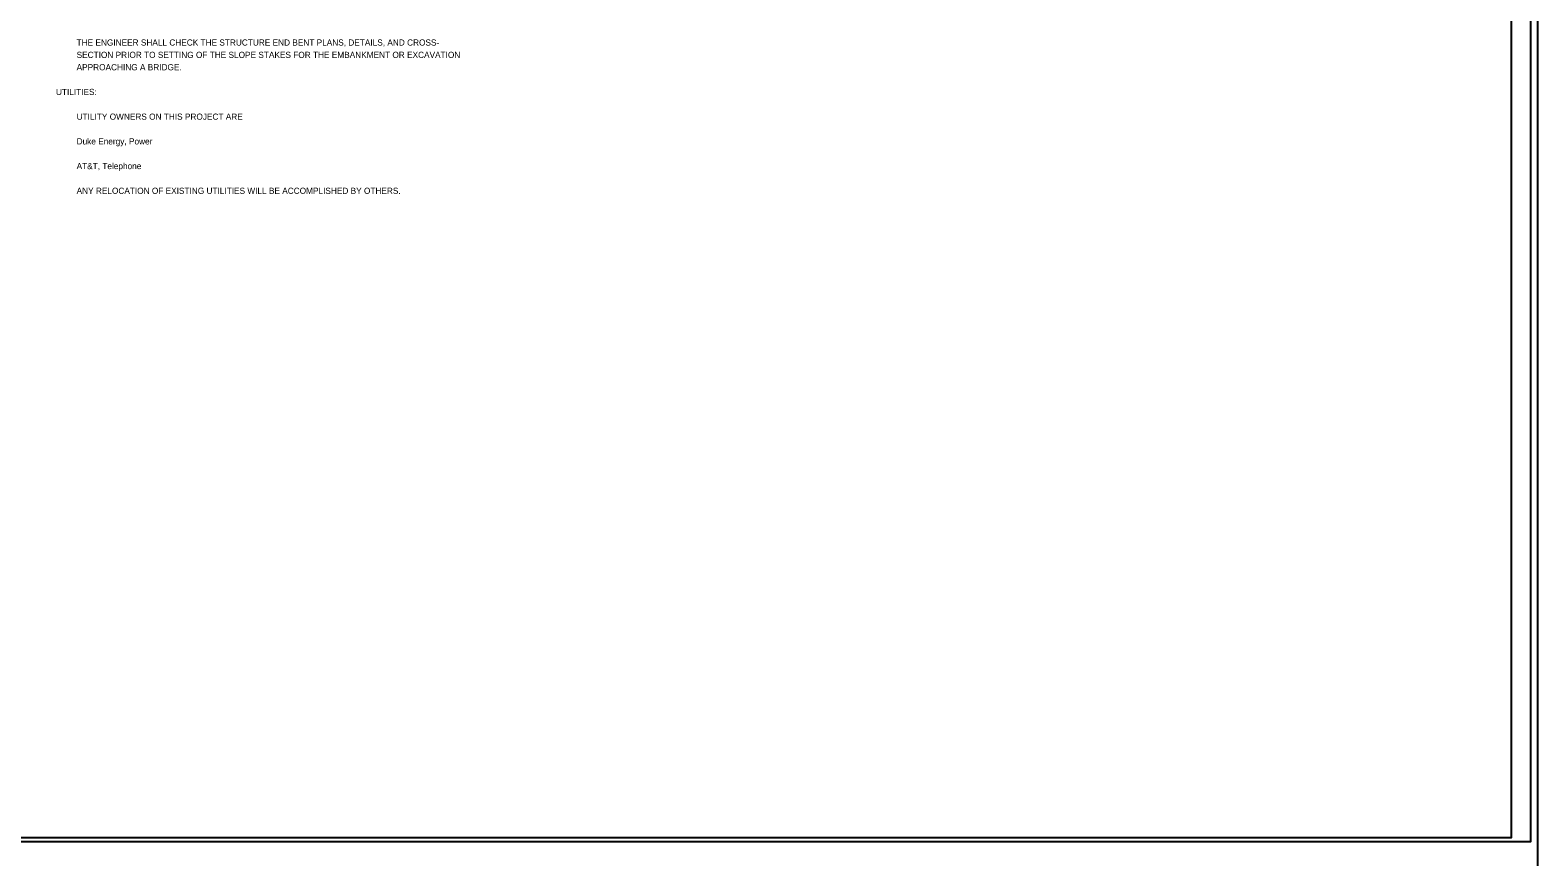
# Model space of a CAD drawing. Extents: x 1974126 to 1975810, y 438878 to 442173.
# Drawn here: x 1974833 to 1975809, y 441088 to 441624 of the extents above; entities that cross this region are included whole.
import ezdxf

# ---------------------------------------------------------------- set-up
doc = ezdxf.new("R2010")
doc.units = 0
for name, color, linetype in [('Default', 7, 'Continuous'), ('Sheet Plan CELL', 7, 'Continuous'), ('Sheet Plot Border Inside CELL', 7, 'Continuous'), ('Sheet Plot Border Outside CELL', 7, 'Continuous')]:
    doc.layers.add(name, color=color, linetype=linetype)

msp = doc.modelspace()

# ---------------------------------------------------------------- linework, layer by layer
at = {"layer": 'Sheet Plan CELL'}
msp.add_lwpolyline([(1975792.14, 442150.79), (1974292.14, 442150.79), (1974292.14, 441100.79), (1975792.14, 441100.79)], close=True, dxfattribs=at)
at = {"layer": 'Sheet Plot Border Inside CELL'}
msp.add_lwpolyline([(1974138.64, 441098.29), (1975804.64, 441098.29), (1975804.64, 442153.29), (1974138.64, 442153.29)], close=True, dxfattribs=at)
at = {"layer": 'Sheet Plot Border Outside CELL'}
msp.add_lwpolyline([(1974125.64, 441078.29), (1975809.14, 441078.29), (1975809.14, 442173.29), (1974125.64, 442173.29)], close=True, dxfattribs=at)

# ---------------------------------------------------------------- texts
at = {"layer": 'Default'}
for s, p in [('         THE ENGINEER SHALL CHECK THE STRUCTURE END BENT PLANS, DETAILS, AND CROSS-', (1974849.54, 441613.54)), ('         SECTION PRIOR TO SETTING OF THE SLOPE STAKES FOR THE EMBANKMENT OR EXCAVATION ', (1974849.54, 441605.54)), ('         APPROACHING A BRIDGE.  ', (1974849.54, 441597.54)), ('UTILITIES:  ', (1974849.54, 441581.54)), ('         UTILITY OWNERS ON THIS PROJECT ARE   ', (1974849.54, 441565.54)), ('         Duke Energy, Power', (1974849.54, 441549.54)), ('         AT&T, Telephone', (1974849.54, 441533.54)), ('         ANY RELOCATION OF EXISTING UTILITIES WILL BE ACCOMPLISHED BY OTHERS.  ', (1974849.54, 441517.54))]:
    msp.add_text(s, height=4, dxfattribs=at).set_placement(p)

doc.saveas('drawing.dxf')
